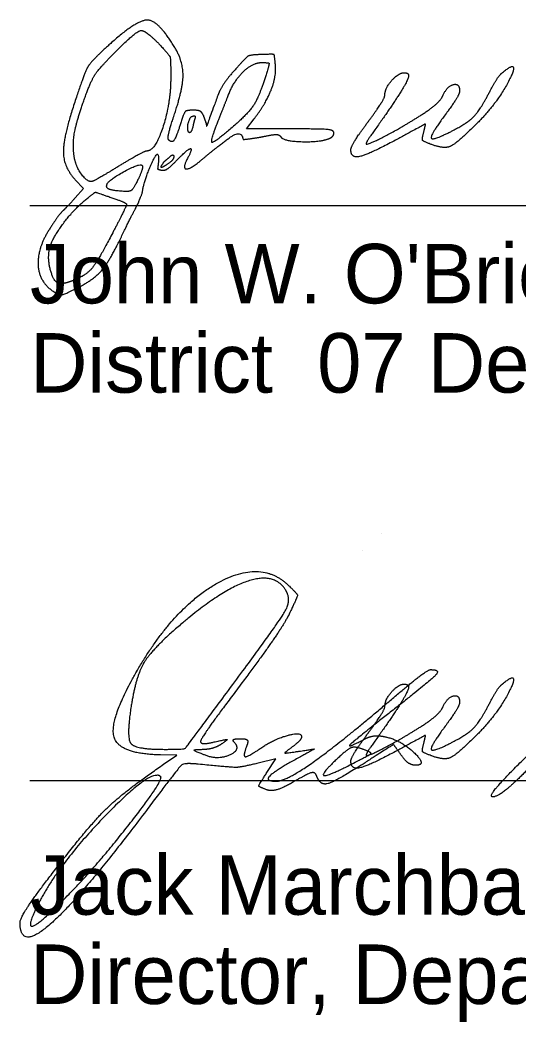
# Model space of a CAD drawing. Extents: x 0 to 34, y 0 to 22.
# Drawn here: x 24.504 to 25.679, y 6.366 to 8.723 of the extents above; entities that cross this region are included whole.
import ezdxf

# ---------------------------------------------------------------- set-up
doc = ezdxf.new("R2010")
doc.units = 0
doc.layers.add('SH_Data', color=7, linetype='Continuous')
doc.layers.add('SH_Text', color=7, linetype='Continuous')

msp = doc.modelspace()

# ---------------------------------------------------------------- linework, layer by layer
at = {"layer": 'SH_Data'}
for p, q in [((24.5279, 8.2866), (28.0279, 8.2866)), ((24.5279, 6.9345), (28.0279, 6.9345))]:
    msp.add_line(p, q, dxfattribs=at)
at = {"layer": 'SH_Text'}
for p, q in [((25.3555, 7.5158), (25.3555, 7.5158)), ((25.3107, 7.4742), (25.3107, 7.4742)), ((24.9902, 7.1396), (24.9902, 7.1396))]:
    msp.add_line(p, q, dxfattribs=at)
for points in [[(25.1404, 8.467), (25.0375, 8.467), (25.0558, 8.491)], [(24.6346, 8.3476), (24.654, 8.327), (24.6346, 8.3052)], [(24.8425, 6.9726), (24.8732, 6.9938), (24.8354, 6.9945)], [(25.0855, 6.9528), (25.1067, 6.9851), (25.0649, 6.975)]]:
    msp.add_lwpolyline(points, dxfattribs=at)
for points in [[(24.8676, 8.6605), (24.8304, 8.7215), (24.781, 8.7246), (24.7199, 8.6699)], [(24.7219, 8.641), (24.7758, 8.6962), (24.8, 8.7007), (24.836, 8.6621)], [(24.7199, 8.6699), (24.6737, 8.6285), (24.656, 8.5996), (24.6319, 8.526)], [(24.836, 8.6621), (24.8564, 8.6403), (24.8592, 8.6313), (24.8592, 8.5881)], [(24.8663, 8.4961), (24.888, 8.5601), (24.8885, 8.6263), (24.8676, 8.6605)], [(24.6595, 8.547), (24.672, 8.5811), (24.69, 8.6082), (24.7219, 8.641)], [(25.0723, 8.642), (25.0465, 8.6411), (25.0363, 8.6352), (25.0106, 8.6062)], [(25.1056, 8.6185), (25.1034, 8.6413), (25.1012, 8.6429), (25.0723, 8.642)], [(25.0106, 8.6062), (24.9936, 8.5871), (24.976, 8.5614), (24.9715, 8.5492)], [(24.9955, 8.5481), (25.008, 8.5802), (25.052, 8.623), (25.0726, 8.623)], [(25.0869, 8.605), (25.0699, 8.5491), (25.0454, 8.5072), (25.013, 8.4787)], [(25.0558, 8.491), (25.0834, 8.5271), (25.1083, 8.591), (25.1056, 8.6185)], [(25.0726, 8.623), (25.0893, 8.623), (25.0915, 8.6202), (25.0869, 8.605)], [(25.64, 8.5996), (25.6828, 8.6351), (25.629, 8.5287), (25.5787, 8.4786)], [(24.8592, 8.5881), (24.8592, 8.5281), (24.8225, 8.415), (24.803, 8.415)], [(25.4192, 8.5918), (25.4192, 8.5839), (25.3786, 8.519), (25.3398, 8.465)], [(25.3632, 8.547), (25.3632, 8.562), (25.3949, 8.599), (25.4078, 8.599)], [(25.4078, 8.599), (25.4141, 8.599), (25.4192, 8.5957), (25.4192, 8.5918)], [(25.611, 8.5564), (25.6205, 8.5748), (25.6335, 8.5942), (25.64, 8.5996)], [(25.5007, 8.547), (25.5102, 8.5678), (25.5392, 8.5749), (25.5392, 8.5564)], [(25.5392, 8.5564), (25.5392, 8.5506), (25.5248, 8.5265), (25.5072, 8.5029)], [(25.5203, 8.4616), (25.5584, 8.4812), (25.5884, 8.5125), (25.611, 8.5564)], [(24.6328, 8.3975), (24.6272, 8.4268), (24.6384, 8.4895), (24.6595, 8.547)], [(24.9715, 8.5492), (24.9427, 8.4717), (24.9449, 8.4753), (24.9381, 8.4939)], [(24.9722, 8.489), (24.9814, 8.5121), (24.9919, 8.5387), (24.9955, 8.5481)], [(25.3232, 8.483), (25.3452, 8.5128), (25.3632, 8.5416), (25.3632, 8.547)], [(25.4494, 8.5001), (25.4726, 8.5149), (25.4957, 8.536), (25.5007, 8.547)], [(24.6319, 8.526), (24.6059, 8.4468), (24.607, 8.377), (24.6346, 8.3476)], [(24.9121, 8.511), (24.8965, 8.511), (24.8905, 8.5049), (24.8829, 8.481)], [(24.9381, 8.4939), (24.934, 8.505), (24.9249, 8.511), (24.9121, 8.511)], [(24.8545, 8.441), (24.8517, 8.4438), (24.8571, 8.4686), (24.8663, 8.4961)], [(24.8992, 8.4705), (24.8992, 8.4746), (24.8998, 8.4802), (24.9062, 8.4949)], [(24.9062, 8.4949), (24.9197, 8.5015), (24.913, 8.4825), (24.9118, 8.4746)], [(25.013, 8.4787), (24.962, 8.4338), (24.9513, 8.4365), (24.9722, 8.489)], [(25.3196, 8.431), (25.3278, 8.431), (25.4081, 8.4737), (25.4494, 8.5001)], [(25.5072, 8.5029), (25.47, 8.4531), (25.4747, 8.4382), (25.5203, 8.4616)], [(24.8829, 8.481), (24.8723, 8.4477), (24.8621, 8.4334), (24.8545, 8.441)], [(24.9118, 8.4746), (24.9078, 8.4573), (24.8992, 8.459), (24.8992, 8.4705)], [(25.2432, 8.4578), (25.2432, 8.4642), (25.2122, 8.467), (25.1404, 8.467)], [(25.2832, 8.4179), (25.2832, 8.4239), (25.3012, 8.4532), (25.3232, 8.483)], [(25.3398, 8.465), (25.3264, 8.4463), (25.3173, 8.431), (25.3196, 8.431)], [(25.4546, 8.4592), (25.4595, 8.4787), (25.4579, 8.4783), (25.3928, 8.4431)], [(25.5787, 8.4786), (25.5329, 8.4328), (25.5023, 8.4191), (25.4719, 8.4307)], [(24.9324, 8.3947), (24.9663, 8.4233), (25.0264, 8.4674), (25.0295, 8.4421)], [(25.0295, 8.4421), (25.0437, 8.4435), (25.0683, 8.4473), (25.0843, 8.4505)], [(25.0843, 8.4505), (25.1028, 8.4543), (25.1154, 8.4532), (25.1188, 8.4477)], [(25.1188, 8.4477), (25.1245, 8.4385), (25.209, 8.4356), (25.2306, 8.4438)], [(25.2306, 8.4438), (25.2375, 8.4465), (25.2432, 8.4528), (25.2432, 8.4578)], [(25.3928, 8.4431), (25.3258, 8.4069), (25.2832, 8.3971), (25.2832, 8.4179)], [(25.4719, 8.4307), (25.4533, 8.4378), (25.4504, 8.4425), (25.4546, 8.4592)], [(24.803, 8.415), (24.7991, 8.415), (24.7691, 8.3988), (24.7365, 8.379)], [(24.8708, 8.3905), (24.8973, 8.4181), (24.9119, 8.4227), (24.8995, 8.3994)], [(24.6725, 8.343), (24.6619, 8.343), (24.6366, 8.3777), (24.6328, 8.3975)], [(24.792, 8.3148), (24.7951, 8.3437), (24.8361, 8.4331), (24.8283, 8.3725)], [(24.8283, 8.3725), (24.8419, 8.3675), (24.8569, 8.376), (24.8708, 8.3905)], [(24.8603, 8.3904), (24.8459, 8.3797), (24.833, 8.3742), (24.841, 8.3861)], [(24.841, 8.3861), (24.8436, 8.3898), (24.8482, 8.3938), (24.8544, 8.3989)], [(24.8544, 8.3989), (24.8647, 8.4093), (24.8678, 8.3983), (24.8603, 8.3904)], [(24.8995, 8.3994), (24.886, 8.3742), (24.9047, 8.3714), (24.9324, 8.3947)], [(24.7365, 8.379), (24.7039, 8.3592), (24.6751, 8.343), (24.6725, 8.343)], [(24.709, 8.3362), (24.7125, 8.3467), (24.786, 8.3868), (24.7916, 8.3813)], [(24.7916, 8.3813), (24.794, 8.3789), (24.7897, 8.3639), (24.7821, 8.348)], [(24.7821, 8.348), (24.7724, 8.3277), (24.7633, 8.3192), (24.7518, 8.3199)], [(24.7518, 8.3199), (24.7233, 8.3215), (24.7062, 8.328), (24.709, 8.3362)], [(24.5745, 8.1868), (24.5802, 8.2095), (24.631, 8.2777), (24.6594, 8.3008)], [(24.6346, 8.3052), (24.624, 8.2932), (24.6112, 8.2797), (24.6063, 8.2752)], [(24.6594, 8.3008), (24.6806, 8.318), (24.6826, 8.3182), (24.7183, 8.306)], [(24.7183, 8.306), (24.7386, 8.2991), (24.7552, 8.2916), (24.7552, 8.2894)], [(24.7792, 8.2863), (24.7828, 8.2913), (24.7859, 8.3018), (24.792, 8.3148)], [(24.6063, 8.2752), (24.6013, 8.2707), (24.5878, 8.2526), (24.5763, 8.2351)], [(24.7552, 8.2894), (24.7552, 8.2872), (24.7405, 8.2571), (24.7226, 8.2226)], [(24.7491, 8.2257), (24.7618, 8.2525), (24.7762, 8.2794), (24.7792, 8.2863)], [(24.5763, 8.2351), (24.5453, 8.1883), (24.5487, 8.1076), (24.5824, 8.0851)], [(24.6426, 8.0947), (24.6803, 8.1139), (24.7185, 8.1608), (24.7491, 8.2257)], [(24.7226, 8.2226), (24.688, 8.1562), (24.6592, 8.1216), (24.6287, 8.11)], [(24.599, 8.103), (24.5855, 8.103), (24.5682, 8.1619), (24.5745, 8.1868)], [(24.6287, 8.11), (24.6185, 8.1061), (24.6052, 8.103), (24.599, 8.103)], [(24.5824, 8.0851), (24.5964, 8.0757), (24.6097, 8.0779), (24.6426, 8.0947)], [(24.7789, 7.1903), (24.8651, 7.3407), (25.0732, 7.4567), (25.1389, 7.3911)], [(25.1299, 7.3819), (25.104, 7.4239), (24.9779, 7.3827), (24.8825, 7.3011)], [(24.9902, 7.1396), (25.1115, 7.303), (25.144, 7.3592), (25.1299, 7.3819)], [(25.1389, 7.3911), (25.1577, 7.3723), (25.1577, 7.3672), (25.1394, 7.3288)], [(25.1394, 7.3288), (25.1284, 7.3058), (25.0767, 7.2303), (25.0245, 7.1609)], [(24.8825, 7.3011), (24.8159, 7.2441), (24.7771, 7.18), (24.766, 7.1087)], [(24.8354, 6.9945), (24.7375, 6.9962), (24.7141, 7.0773), (24.7789, 7.1903)], [(25.369, 7.1168), (25.4194, 7.1597), (25.4649, 7.1948), (25.4701, 7.195)], [(25.4701, 7.195), (25.495, 7.1955), (25.4716, 7.1699), (25.3857, 7.1026)], [(25.64, 7.1615), (25.6828, 7.1971), (25.629, 7.0907), (25.5787, 7.0406)], [(25.0245, 7.1609), (24.9722, 7.0916), (24.9295, 7.0309), (24.9295, 7.0261)], [(25.4192, 7.1537), (25.4192, 7.1459), (25.3786, 7.081), (25.3398, 7.0269)], [(25.3632, 7.1089), (25.3632, 7.124), (25.3949, 7.1609), (25.4078, 7.1609)], [(25.4078, 7.1609), (25.4141, 7.1609), (25.4192, 7.1577), (25.4192, 7.1537)], [(25.611, 7.1184), (25.6205, 7.1368), (25.6335, 7.1562), (25.64, 7.1615)], [(24.844, 7.0076), (24.8907, 7.0076), (24.8953, 7.0118), (24.9902, 7.1396)], [(25.5007, 7.1089), (25.5102, 7.1297), (25.5392, 7.1368), (25.5392, 7.1184)], [(25.5392, 7.1184), (25.5392, 7.1126), (25.5248, 7.0885), (25.5072, 7.0648)], [(25.5203, 7.0235), (25.5584, 7.0432), (25.5884, 7.0745), (25.611, 7.1184)], [(24.766, 7.1087), (24.7545, 7.0354), (24.776, 7.0076), (24.844, 7.0076)], [(25.1076, 6.9326), (25.1307, 6.9326), (25.2567, 7.0214), (25.369, 7.1168)], [(25.3857, 7.1026), (25.2925, 7.0296), (25.271, 7.0081), (25.315, 7.0316)], [(25.3232, 7.0449), (25.3452, 7.0747), (25.3632, 7.1035), (25.3632, 7.1089)], [(25.4494, 7.062), (25.4726, 7.0768), (25.4957, 7.098), (25.5007, 7.1089)], [(25.3196, 6.9929), (25.3278, 6.9929), (25.4081, 7.0357), (25.4494, 7.062)], [(25.5072, 7.0648), (25.47, 7.015), (25.4747, 7.0001), (25.5203, 7.0235)], [(24.9295, 7.0261), (24.9295, 7.0213), (24.9449, 7.021), (24.9638, 7.0254)], [(24.9399, 6.9944), (24.9698, 6.9824), (25.026, 7.007), (25.0086, 7.0244)], [(24.9638, 7.0254), (24.9894, 7.0313), (24.9934, 7.0301), (24.9795, 7.0207)], [(25.0086, 7.0244), (25.004, 7.0289), (25.0103, 7.0326), (25.0225, 7.0326)], [(25.0225, 7.0326), (25.037, 7.0326), (25.0422, 7.0262), (25.0375, 7.0139)], [(25.0736, 7.012), (25.1025, 7.0318), (25.167, 7.0493), (25.167, 7.0374)], [(25.167, 7.0374), (25.167, 7.0329), (25.1572, 7.022), (25.1453, 7.0133)], [(25.2832, 6.9798), (25.2832, 6.9858), (25.3012, 7.0151), (25.3232, 7.0449)], [(25.315, 7.0316), (25.3276, 7.0383), (25.3515, 7.0404), (25.3681, 7.0362)], [(25.3398, 7.0269), (25.3264, 7.0082), (25.3173, 6.9929), (25.3196, 6.9929)], [(25.3681, 7.0362), (25.4042, 7.0271), (25.4625, 6.9701), (25.4358, 6.9701)], [(25.4546, 7.0212), (25.4595, 7.0407), (25.4579, 7.0403), (25.3928, 7.0051)], [(25.5787, 7.0406), (25.5329, 6.9948), (25.5023, 6.9811), (25.4719, 6.9927)], [(24.9357, 7.007), (24.9133, 7.0062), (24.9138, 7.0048), (24.9399, 6.9944)], [(24.9795, 7.0207), (24.9692, 7.0137), (24.9495, 7.0076), (24.9357, 7.007)], [(25.0375, 7.0139), (25.0285, 6.9906), (25.0414, 6.99), (25.0736, 7.012)], [(25.1453, 7.0133), (25.1264, 6.9995), (25.1284, 6.9982), (25.161, 7.0031)], [(25.161, 7.0031), (25.1977, 7.0087), (25.1976, 7.0084), (25.1522, 6.9833)], [(25.3107, 7.008), (25.2935, 7.0144), (25.277, 7.0093), (25.2576, 6.9915)], [(25.2826, 6.9717), (25.329, 6.9954), (25.3325, 7), (25.3107, 7.008)], [(25.3928, 7.0051), (25.3258, 6.9689), (25.2832, 6.9591), (25.2832, 6.9798)], [(25.4011, 6.9948), (25.3843, 7.0189), (25.3822, 7.0184), (25.3165, 6.9761)], [(25.4719, 6.9927), (25.4533, 6.9998), (25.4504, 7.0045), (25.4546, 7.0212)], [(25.617, 6.8958), (25.6067, 6.896), (25.6563, 6.9522), (25.7273, 7.0207)], [(25.1522, 6.9833), (25.1011, 6.9551), (25.0814, 6.9326), (25.1076, 6.9326)], [(25.3165, 6.9761), (25.2476, 6.9317), (25.2101, 6.922), (25.202, 6.9463)], [(25.2576, 6.9915), (25.2133, 6.951), (25.2246, 6.9421), (25.2826, 6.9717)], [(25.4358, 6.9701), (25.4262, 6.9701), (25.4106, 6.9812), (25.4011, 6.9948)], [(24.5916, 6.7304), (24.6692, 6.8309), (24.7493, 6.9082), (24.8425, 6.9726)], [(24.9237, 6.9727), (24.8903, 6.976), (24.8786, 6.9655), (24.8019, 6.8639)], [(25.0649, 6.975), (25.0246, 6.9653), (25.0023, 6.9649), (24.9237, 6.9727)], [(25.0843, 6.9127), (25.0661, 6.9197), (25.0662, 6.9233), (25.0855, 6.9528)], [(25.202, 6.9463), (25.1991, 6.9549), (25.1799, 6.9497), (25.1508, 6.9325)], [(25.7045, 6.9655), (25.6667, 6.927), (25.6273, 6.8957), (25.617, 6.8958)], [(24.8354, 6.9434), (24.8145, 6.9643), (24.596, 6.7386), (24.5497, 6.6483)], [(24.6198, 6.667), (24.6874, 6.7361), (24.8431, 6.9357), (24.8354, 6.9434)], [(25.1508, 6.9325), (25.1252, 6.9174), (25.0953, 6.9085), (25.0843, 6.9127)], [(24.8019, 6.8639), (24.6496, 6.6618), (24.5045, 6.5332), (24.5045, 6.6002)], [(24.5045, 6.6002), (24.5045, 6.6098), (24.5437, 6.6684), (24.5916, 6.7304)], [(24.5497, 6.6483), (24.5184, 6.5873), (24.55, 6.5958), (24.6198, 6.667)]]:
    msp.add_open_spline(points, degree=2, dxfattribs=at)

# ---------------------------------------------------------------- texts
for s, p in [("John W. O'Brien", (24.5279, 8.0566)), ('District  07 Deputy Director', (24.5279, 7.8466)), ('Jack Marchbanks, PhD', (24.5279, 6.6186)), ('Director, Department of Transportation', (24.5279, 6.4086))]:
    msp.add_text(s, height=0.14, dxfattribs=at).set_placement(p)

doc.saveas('drawing.dxf')
